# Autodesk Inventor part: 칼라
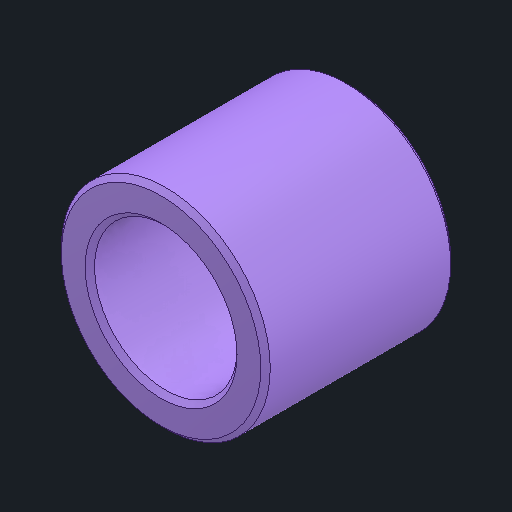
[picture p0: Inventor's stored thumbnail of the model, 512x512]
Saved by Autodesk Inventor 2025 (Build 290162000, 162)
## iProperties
Created: 2025-08
Part Number: 칼라
Material: 스테인리스강
Document SubType Name: Modeling
Designer: infra005
Density: 8.08 g/cm^3
Appearance: 기본값
Author: jhkim
Sending System: Autodesk Inventor 2026
Preprocessor: ST-DEVELOPER v20.1
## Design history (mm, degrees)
feature "솔리드1"
node "솔리드2"
